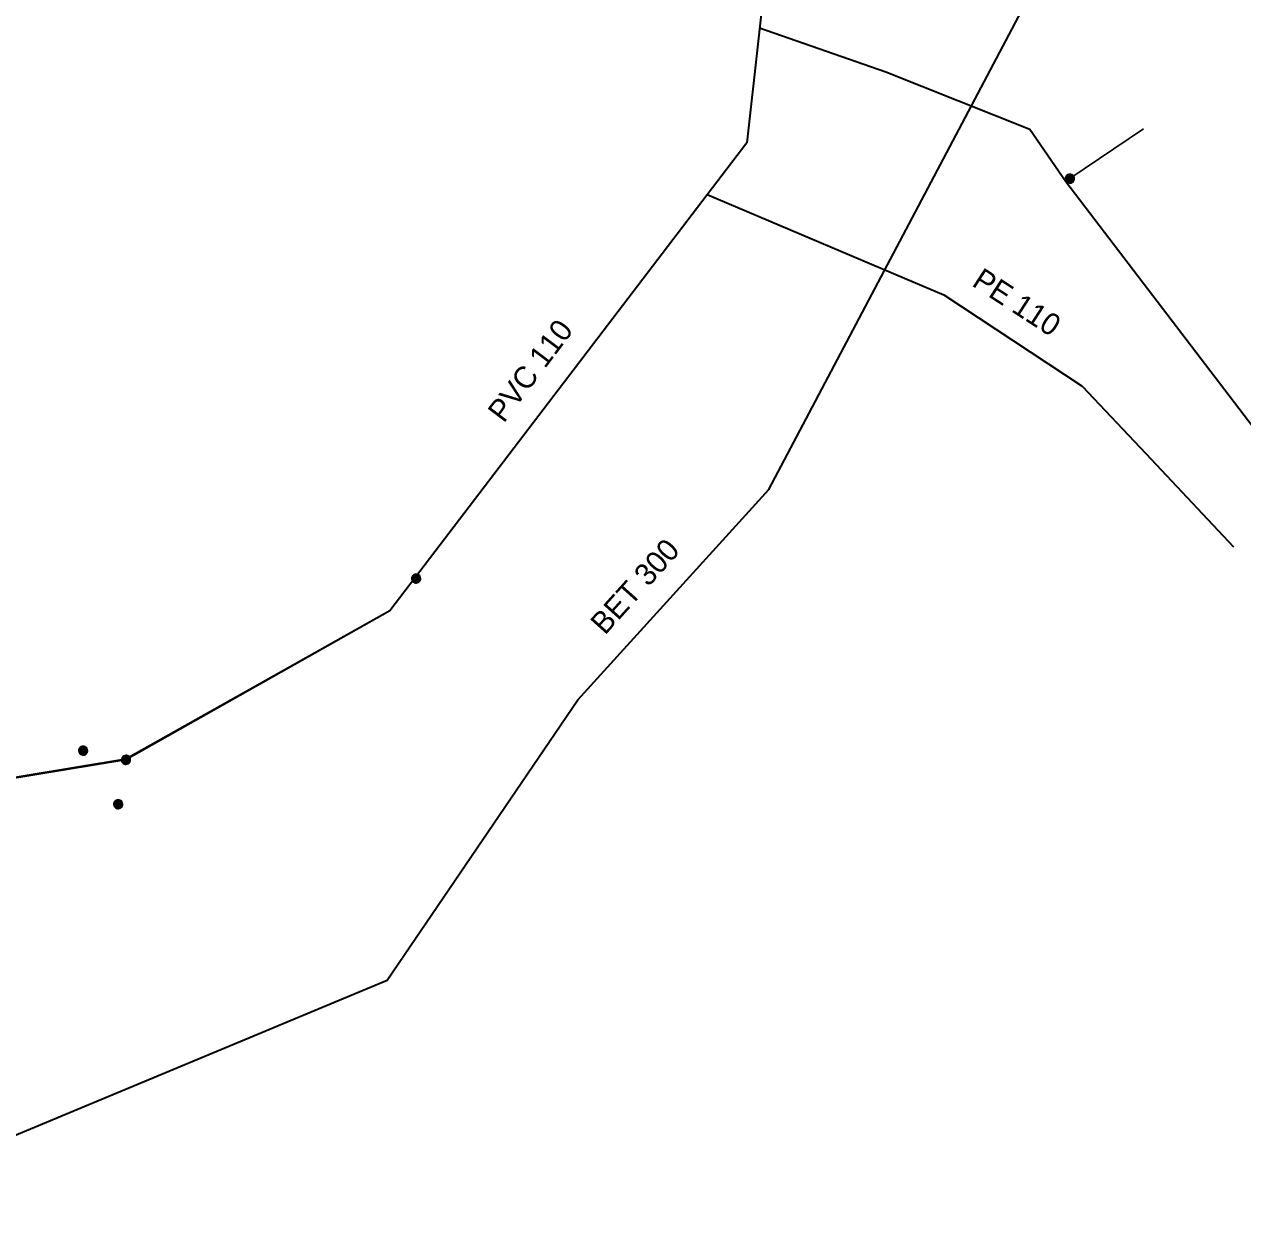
# Model space of a CAD drawing. Extents: x -873619 to -867639, y -1015082 to -1012326.
# Drawn here: x -868016.1 to -867954.9, y -1012860 to -1012799.5 of the extents above; entities that cross this region are included whole.
import ezdxf

# ---------------------------------------------------------------- set-up
doc = ezdxf.new("R2010")
doc.units = 0
doc.header["$LTSCALE"] = 0.44
for name, color, linetype, lineweight in [('1', 7, 'Continuous', 13), ('10', 7, 'Continuous', 13), ('12', 7, 'Continuous', 13), ('21', 7, 'Continuous', 35), ('25', 7, 'Continuous', 13), ('3', 7, 'Continuous', 25), ('32', 7, 'Continuous', 13)]:
    doc.layers.add(name, color=color, linetype=linetype, lineweight=lineweight)

msp = doc.modelspace()

# ---------------------------------------------------------------- linework, layer by layer
at = {"layer": '1', "lineweight": 35}
for points in [[(-867974.611, -1012725.697), (-867976.949, -1012730.385), (-867980.624, -1012763.205), (-867983.112, -1012775.195), (-867978.719, -1012795.525), (-867979.823, -1012805.464), (-867997.768, -1012829.005), (-868011.042, -1012836.499), (-868058.95, -1012844.4), (-868077.43, -1012833.46), (-868085.171, -1012827.86)], [(-867979.181, -1012799.683), (-867972.83, -1012801.89), (-867965.59, -1012804.78), (-867963.787, -1012807.409), (-867948.768, -1012827.087), (-867948.538, -1012827.407), (-867943.513, -1012834.828), (-867938.476, -1012842.701), (-867934.013, -1012848.778), (-867931.689, -1012852.506), (-867924.702, -1012862.569), (-867923.496, -1012864.901), (-867916.531, -1012874.592), (-867908.231, -1012887.091), (-867905.717, -1012890.99), (-867899.122, -1012900.29), (-867892.55, -1012910.082), (-867889.71, -1012914.412), (-867888.18, -1012916.7), (-867891.84, -1012919), (-867886.89, -1012927.31), (-867886.728, -1012931.158)], [(-867981.811, -1012808.072), (-867969.919, -1012813.11), (-867962.96, -1012817.7), (-867959.76, -1012821.1), (-867955.36, -1012825.78)], [(-867997.768, -1012829.005), (-868011.041, -1012836.459), (-868058.95, -1012844.4)]]:
    msp.add_lwpolyline(points, dxfattribs=at)
at = {"layer": '10'}
for points in [[(-867996.218, -1012827.381), (-867996.225, -1012827.329), (-867996.242, -1012827.279), (-867996.271, -1012827.235), (-867996.308, -1012827.198), (-867996.353, -1012827.171), (-867996.402, -1012827.154), (-867996.456, -1012827.15), (-867996.507, -1012827.157), (-867996.556, -1012827.176), (-867996.6, -1012827.205), (-867996.636, -1012827.244), (-867996.662, -1012827.289), (-867996.678, -1012827.34), (-867996.681, -1012827.392), (-867996.673, -1012827.444), (-867996.652, -1012827.493), (-867996.622, -1012827.536), (-867996.583, -1012827.57), (-867996.537, -1012827.596), (-867996.485, -1012827.61), (-867996.433, -1012827.612), (-867996.382, -1012827.602), (-867996.333, -1012827.581), (-867996.291, -1012827.55), (-867996.257, -1012827.509), (-867996.233, -1012827.463), (-867996.22, -1012827.412)], [(-867996.249, -1012827.381), (-867996.255, -1012827.332), (-867996.272, -1012827.286), (-867996.299, -1012827.246), (-867996.337, -1012827.214), (-867996.38, -1012827.192), (-867996.429, -1012827.181), (-867996.478, -1012827.181), (-867996.524, -1012827.194), (-867996.568, -1012827.218), (-867996.603, -1012827.251), (-867996.63, -1012827.292), (-867996.647, -1012827.339), (-867996.651, -1012827.388), (-867996.644, -1012827.436), (-867996.625, -1012827.481), (-867996.595, -1012827.521), (-867996.556, -1012827.552), (-867996.512, -1012827.572), (-867996.465, -1012827.582), (-867996.416, -1012827.58), (-867996.369, -1012827.565), (-867996.326, -1012827.54), (-867996.291, -1012827.506), (-867996.266, -1012827.464), (-867996.252, -1012827.417)], [(-867996.279, -1012827.381), (-867996.284, -1012827.336), (-867996.301, -1012827.294), (-867996.33, -1012827.259), (-867996.365, -1012827.232), (-867996.407, -1012827.215), (-867996.453, -1012827.21), (-867996.497, -1012827.216), (-867996.539, -1012827.235), (-867996.573, -1012827.263), (-867996.6, -1012827.3), (-867996.617, -1012827.342), (-867996.62, -1012827.387), (-867996.614, -1012827.432), (-867996.595, -1012827.473), (-867996.566, -1012827.507), (-867996.529, -1012827.533), (-867996.485, -1012827.549), (-867996.441, -1012827.552), (-867996.396, -1012827.544), (-867996.355, -1012827.524), (-867996.321, -1012827.495), (-867996.296, -1012827.457), (-867996.282, -1012827.414)], [(-867996.309, -1012827.381), (-867996.313, -1012827.34), (-867996.331, -1012827.303), (-867996.358, -1012827.272), (-867996.394, -1012827.251), (-867996.434, -1012827.24), (-867996.475, -1012827.242), (-867996.514, -1012827.255), (-867996.548, -1012827.279), (-867996.573, -1012827.311), (-867996.588, -1012827.349), (-867996.59, -1012827.39), (-867996.583, -1012827.43), (-867996.563, -1012827.466), (-867996.534, -1012827.495), (-867996.497, -1012827.514), (-867996.456, -1012827.522), (-867996.416, -1012827.518), (-867996.377, -1012827.503), (-867996.345, -1012827.477), (-867996.323, -1012827.443), (-867996.309, -1012827.404)], [(-867996.338, -1012827.381), (-867996.343, -1012827.345), (-867996.362, -1012827.313), (-867996.387, -1012827.288), (-867996.421, -1012827.273), (-867996.458, -1012827.27), (-867996.492, -1012827.278), (-867996.524, -1012827.298), (-867996.546, -1012827.326), (-867996.559, -1012827.36), (-867996.559, -1012827.397), (-867996.549, -1012827.432), (-867996.527, -1012827.461), (-867996.497, -1012827.482), (-867996.463, -1012827.492), (-867996.426, -1012827.49), (-867996.392, -1012827.476), (-867996.365, -1012827.453), (-867996.345, -1012827.421), (-867996.338, -1012827.386)], [(-867996.369, -1012827.381), (-867996.374, -1012827.35), (-867996.391, -1012827.324), (-867996.416, -1012827.307), (-867996.446, -1012827.3), (-867996.478, -1012827.304), (-867996.505, -1012827.321), (-867996.522, -1012827.345), (-867996.531, -1012827.376), (-867996.527, -1012827.406), (-867996.512, -1012827.434), (-867996.487, -1012827.453), (-867996.458, -1012827.462), (-867996.426, -1012827.459), (-867996.399, -1012827.445), (-867996.379, -1012827.421), (-867996.369, -1012827.392)], [(-867996.399, -1012827.381), (-867996.404, -1012827.357), (-867996.421, -1012827.339), (-867996.443, -1012827.33), (-867996.468, -1012827.333), (-867996.489, -1012827.347), (-867996.5, -1012827.369), (-867996.5, -1012827.394), (-867996.487, -1012827.415), (-867996.468, -1012827.429), (-867996.443, -1012827.432), (-867996.419, -1012827.423), (-867996.404, -1012827.405)], [(-867996.429, -1012827.381), (-867996.434, -1012827.366), (-867996.448, -1012827.36), (-867996.463, -1012827.364), (-867996.47, -1012827.378), (-867996.467, -1012827.393), (-867996.453, -1012827.402), (-867996.438, -1012827.399), (-867996.429, -1012827.387)], [(-868010.811, -1012836.499), (-868010.817, -1012836.447), (-868010.834, -1012836.397), (-868010.863, -1012836.353), (-868010.9, -1012836.316), (-868010.945, -1012836.289), (-868010.995, -1012836.272), (-868011.048, -1012836.268), (-868011.1, -1012836.275), (-868011.149, -1012836.294), (-868011.192, -1012836.323), (-868011.228, -1012836.362), (-868011.254, -1012836.407), (-868011.27, -1012836.458), (-868011.273, -1012836.51), (-868011.265, -1012836.562), (-868011.245, -1012836.611), (-868011.214, -1012836.654), (-868011.175, -1012836.688), (-868011.129, -1012836.714), (-868011.078, -1012836.728), (-868011.025, -1012836.73), (-868010.974, -1012836.72), (-868010.926, -1012836.699), (-868010.883, -1012836.668), (-868010.849, -1012836.627), (-868010.825, -1012836.581), (-868010.813, -1012836.53)], [(-868010.841, -1012836.499), (-868010.847, -1012836.45), (-868010.864, -1012836.404), (-868010.892, -1012836.364), (-868010.929, -1012836.332), (-868010.973, -1012836.31), (-868011.021, -1012836.299), (-868011.07, -1012836.299), (-868011.117, -1012836.312), (-868011.16, -1012836.336), (-868011.196, -1012836.369), (-868011.223, -1012836.41), (-868011.239, -1012836.457), (-868011.243, -1012836.506), (-868011.236, -1012836.554), (-868011.217, -1012836.599), (-868011.187, -1012836.639), (-868011.149, -1012836.67), (-868011.105, -1012836.69), (-868011.057, -1012836.7), (-868011.008, -1012836.698), (-868010.961, -1012836.683), (-868010.918, -1012836.658), (-868010.884, -1012836.624), (-868010.858, -1012836.582), (-868010.844, -1012836.535)], [(-868010.871, -1012836.499), (-868010.877, -1012836.454), (-868010.894, -1012836.412), (-868010.922, -1012836.377), (-868010.958, -1012836.35), (-868011, -1012836.333), (-868011.045, -1012836.328), (-868011.09, -1012836.334), (-868011.131, -1012836.353), (-868011.166, -1012836.381), (-868011.193, -1012836.418), (-868011.209, -1012836.46), (-868011.213, -1012836.505), (-868011.206, -1012836.55), (-868011.187, -1012836.591), (-868011.158, -1012836.625), (-868011.121, -1012836.651), (-868011.078, -1012836.667), (-868011.033, -1012836.67), (-868010.988, -1012836.662), (-868010.948, -1012836.642), (-868010.914, -1012836.613), (-868010.888, -1012836.575), (-868010.874, -1012836.532)], [(-868010.901, -1012836.499), (-868010.906, -1012836.458), (-868010.924, -1012836.421), (-868010.951, -1012836.39), (-868010.986, -1012836.369), (-868011.026, -1012836.358), (-868011.067, -1012836.36), (-868011.106, -1012836.373), (-868011.14, -1012836.397), (-868011.165, -1012836.429), (-868011.18, -1012836.467), (-868011.183, -1012836.508), (-868011.175, -1012836.548), (-868011.155, -1012836.584), (-868011.126, -1012836.613), (-868011.089, -1012836.632), (-868011.049, -1012836.64), (-868011.008, -1012836.636), (-868010.97, -1012836.621), (-868010.938, -1012836.595), (-868010.915, -1012836.561), (-868010.902, -1012836.522)], [(-868010.931, -1012836.499), (-868010.936, -1012836.463), (-868010.954, -1012836.431), (-868010.98, -1012836.406), (-868011.014, -1012836.391), (-868011.05, -1012836.388), (-868011.085, -1012836.396), (-868011.116, -1012836.416), (-868011.139, -1012836.444), (-868011.152, -1012836.478), (-868011.152, -1012836.515), (-868011.141, -1012836.55), (-868011.12, -1012836.579), (-868011.09, -1012836.6), (-868011.055, -1012836.61), (-868011.018, -1012836.608), (-868010.984, -1012836.594), (-868010.957, -1012836.571), (-868010.938, -1012836.539), (-868010.931, -1012836.504)], [(-868010.961, -1012836.499), (-868010.966, -1012836.468), (-868010.983, -1012836.442), (-868011.009, -1012836.425), (-868011.039, -1012836.418), (-868011.07, -1012836.422), (-868011.097, -1012836.439), (-868011.115, -1012836.463), (-868011.123, -1012836.494), (-868011.119, -1012836.524), (-868011.104, -1012836.552), (-868011.08, -1012836.571), (-868011.05, -1012836.58), (-868011.019, -1012836.577), (-868010.991, -1012836.563), (-868010.971, -1012836.539), (-868010.961, -1012836.51)], [(-868010.991, -1012836.499), (-868010.996, -1012836.475), (-868011.013, -1012836.457), (-868011.036, -1012836.448), (-868011.06, -1012836.451), (-868011.081, -1012836.465), (-868011.092, -1012836.487), (-868011.092, -1012836.512), (-868011.08, -1012836.533), (-868011.06, -1012836.547), (-868011.035, -1012836.55), (-868011.012, -1012836.541), (-868010.996, -1012836.523)], [(-868011.021, -1012836.499), (-868011.026, -1012836.484), (-868011.041, -1012836.478), (-868011.056, -1012836.482), (-868011.063, -1012836.496), (-868011.059, -1012836.511), (-868011.046, -1012836.52), (-868011.031, -1012836.517), (-868011.021, -1012836.505)]]:
    msp.add_lwpolyline(points, close=True, dxfattribs=at)
at = {"layer": '12'}
for points in [[(-867963.348, -1012807.27), (-867963.355, -1012807.218), (-867963.372, -1012807.168), (-867963.401, -1012807.124), (-867963.438, -1012807.087), (-867963.483, -1012807.06), (-867963.532, -1012807.043), (-867963.586, -1012807.039), (-867963.637, -1012807.046), (-867963.686, -1012807.065), (-867963.73, -1012807.094), (-867963.766, -1012807.133), (-867963.792, -1012807.178), (-867963.808, -1012807.229), (-867963.811, -1012807.281), (-867963.803, -1012807.333), (-867963.782, -1012807.382), (-867963.752, -1012807.425), (-867963.713, -1012807.459), (-867963.667, -1012807.485), (-867963.615, -1012807.499), (-867963.563, -1012807.501), (-867963.512, -1012807.491), (-867963.463, -1012807.47), (-867963.421, -1012807.439), (-867963.387, -1012807.398), (-867963.363, -1012807.352), (-867963.35, -1012807.301)], [(-867963.379, -1012807.27), (-867963.385, -1012807.221), (-867963.402, -1012807.175), (-867963.429, -1012807.135), (-867963.467, -1012807.103), (-867963.511, -1012807.081), (-867963.559, -1012807.07), (-867963.608, -1012807.07), (-867963.654, -1012807.083), (-867963.698, -1012807.107), (-867963.733, -1012807.14), (-867963.761, -1012807.181), (-867963.777, -1012807.228), (-867963.781, -1012807.277), (-867963.774, -1012807.325), (-867963.755, -1012807.37), (-867963.725, -1012807.41), (-867963.686, -1012807.441), (-867963.642, -1012807.461), (-867963.595, -1012807.471), (-867963.546, -1012807.469), (-867963.499, -1012807.454), (-867963.456, -1012807.429), (-867963.421, -1012807.395), (-867963.396, -1012807.353), (-867963.382, -1012807.306)], [(-867963.409, -1012807.27), (-867963.414, -1012807.225), (-867963.431, -1012807.183), (-867963.46, -1012807.148), (-867963.495, -1012807.121), (-867963.538, -1012807.104), (-867963.583, -1012807.099), (-867963.627, -1012807.105), (-867963.669, -1012807.124), (-867963.703, -1012807.152), (-867963.73, -1012807.189), (-867963.747, -1012807.231), (-867963.75, -1012807.276), (-867963.744, -1012807.321), (-867963.725, -1012807.362), (-867963.696, -1012807.396), (-867963.659, -1012807.422), (-867963.615, -1012807.438), (-867963.571, -1012807.441), (-867963.526, -1012807.433), (-867963.485, -1012807.413), (-867963.451, -1012807.384), (-867963.426, -1012807.346), (-867963.412, -1012807.303)], [(-867963.439, -1012807.27), (-867963.443, -1012807.229), (-867963.462, -1012807.192), (-867963.489, -1012807.161), (-867963.524, -1012807.14), (-867963.564, -1012807.129), (-867963.605, -1012807.131), (-867963.644, -1012807.144), (-867963.678, -1012807.168), (-867963.703, -1012807.2), (-867963.718, -1012807.238), (-867963.72, -1012807.279), (-867963.713, -1012807.319), (-867963.693, -1012807.355), (-867963.664, -1012807.384), (-867963.627, -1012807.403), (-867963.587, -1012807.411), (-867963.546, -1012807.407), (-867963.507, -1012807.392), (-867963.475, -1012807.366), (-867963.453, -1012807.332), (-867963.44, -1012807.293)], [(-867963.468, -1012807.27), (-867963.473, -1012807.234), (-867963.492, -1012807.202), (-867963.517, -1012807.177), (-867963.551, -1012807.162), (-867963.588, -1012807.159), (-867963.622, -1012807.167), (-867963.654, -1012807.187), (-867963.676, -1012807.215), (-867963.69, -1012807.249), (-867963.69, -1012807.286), (-867963.679, -1012807.321), (-867963.657, -1012807.35), (-867963.627, -1012807.371), (-867963.593, -1012807.381), (-867963.556, -1012807.379), (-867963.522, -1012807.365), (-867963.495, -1012807.342), (-867963.475, -1012807.31), (-867963.468, -1012807.275)], [(-867963.499, -1012807.27), (-867963.504, -1012807.239), (-867963.521, -1012807.213), (-867963.546, -1012807.196), (-867963.576, -1012807.189), (-867963.608, -1012807.193), (-867963.635, -1012807.21), (-867963.652, -1012807.234), (-867963.661, -1012807.265), (-867963.657, -1012807.295), (-867963.642, -1012807.323), (-867963.617, -1012807.342), (-867963.588, -1012807.351), (-867963.556, -1012807.348), (-867963.529, -1012807.334), (-867963.509, -1012807.31), (-867963.499, -1012807.281)], [(-867963.529, -1012807.27), (-867963.534, -1012807.246), (-867963.551, -1012807.228), (-867963.573, -1012807.219), (-867963.598, -1012807.222), (-867963.619, -1012807.236), (-867963.63, -1012807.258), (-867963.63, -1012807.283), (-867963.617, -1012807.304), (-867963.598, -1012807.318), (-867963.573, -1012807.321), (-867963.549, -1012807.312), (-867963.534, -1012807.294)], [(-867963.559, -1012807.27), (-867963.564, -1012807.255), (-867963.578, -1012807.249), (-867963.593, -1012807.253), (-867963.6, -1012807.267), (-867963.597, -1012807.282), (-867963.583, -1012807.291), (-867963.568, -1012807.288), (-867963.559, -1012807.276)]]:
    msp.add_lwpolyline(points, close=True, dxfattribs=at)
at = {"layer": '21'}
msp.add_lwpolyline([(-868020.287, -1012856.898), (-867997.903, -1012847.584), (-867988.318, -1012833.474), (-867978.718, -1012822.899), (-867965.69, -1012798.22), (-867965.665, -1012798.299)], dxfattribs=at)
at = {"layer": '25'}
for points in [[(-868011.199, -1012838.73), (-868011.205, -1012838.678), (-868011.222, -1012838.628), (-868011.251, -1012838.584), (-868011.288, -1012838.547), (-868011.333, -1012838.52), (-868011.383, -1012838.503), (-868011.436, -1012838.499), (-868011.488, -1012838.506), (-868011.537, -1012838.525), (-868011.58, -1012838.554), (-868011.616, -1012838.593), (-868011.642, -1012838.638), (-868011.658, -1012838.689), (-868011.661, -1012838.741), (-868011.653, -1012838.793), (-868011.633, -1012838.842), (-868011.602, -1012838.885), (-868011.563, -1012838.919), (-868011.517, -1012838.945), (-868011.466, -1012838.959), (-868011.413, -1012838.961), (-868011.362, -1012838.951), (-868011.314, -1012838.93), (-868011.271, -1012838.899), (-868011.237, -1012838.858), (-868011.213, -1012838.812), (-868011.201, -1012838.761)], [(-868011.229, -1012838.73), (-868011.235, -1012838.681), (-868011.252, -1012838.635), (-868011.28, -1012838.595), (-868011.317, -1012838.563), (-868011.361, -1012838.541), (-868011.409, -1012838.53), (-868011.458, -1012838.53), (-868011.505, -1012838.543), (-868011.548, -1012838.567), (-868011.584, -1012838.6), (-868011.611, -1012838.641), (-868011.627, -1012838.688), (-868011.631, -1012838.737), (-868011.624, -1012838.785), (-868011.605, -1012838.83), (-868011.575, -1012838.87), (-868011.537, -1012838.901), (-868011.493, -1012838.921), (-868011.445, -1012838.931), (-868011.396, -1012838.929), (-868011.349, -1012838.914), (-868011.306, -1012838.889), (-868011.272, -1012838.855), (-868011.246, -1012838.813), (-868011.232, -1012838.766)], [(-868011.259, -1012838.73), (-868011.265, -1012838.685), (-868011.282, -1012838.643), (-868011.31, -1012838.608), (-868011.346, -1012838.581), (-868011.388, -1012838.564), (-868011.433, -1012838.559), (-868011.478, -1012838.565), (-868011.519, -1012838.584), (-868011.554, -1012838.612), (-868011.581, -1012838.649), (-868011.597, -1012838.691), (-868011.601, -1012838.736), (-868011.594, -1012838.781), (-868011.575, -1012838.822), (-868011.546, -1012838.856), (-868011.509, -1012838.882), (-868011.466, -1012838.898), (-868011.421, -1012838.901), (-868011.376, -1012838.893), (-868011.336, -1012838.873), (-868011.302, -1012838.844), (-868011.276, -1012838.806), (-868011.262, -1012838.763)], [(-868011.289, -1012838.73), (-868011.294, -1012838.689), (-868011.312, -1012838.652), (-868011.339, -1012838.621), (-868011.374, -1012838.6), (-868011.414, -1012838.589), (-868011.455, -1012838.591), (-868011.494, -1012838.604), (-868011.528, -1012838.628), (-868011.553, -1012838.66), (-868011.568, -1012838.698), (-868011.571, -1012838.739), (-868011.563, -1012838.779), (-868011.543, -1012838.815), (-868011.514, -1012838.844), (-868011.477, -1012838.863), (-868011.437, -1012838.871), (-868011.396, -1012838.867), (-868011.358, -1012838.852), (-868011.326, -1012838.826), (-868011.303, -1012838.792), (-868011.29, -1012838.753)], [(-868011.319, -1012838.73), (-868011.324, -1012838.694), (-868011.342, -1012838.662), (-868011.368, -1012838.637), (-868011.402, -1012838.622), (-868011.438, -1012838.619), (-868011.473, -1012838.627), (-868011.504, -1012838.647), (-868011.527, -1012838.675), (-868011.54, -1012838.709), (-868011.54, -1012838.746), (-868011.529, -1012838.781), (-868011.508, -1012838.81), (-868011.478, -1012838.831), (-868011.443, -1012838.841), (-868011.406, -1012838.839), (-868011.372, -1012838.825), (-868011.345, -1012838.802), (-868011.326, -1012838.77), (-868011.319, -1012838.735)], [(-868011.349, -1012838.73), (-868011.354, -1012838.699), (-868011.371, -1012838.673), (-868011.397, -1012838.656), (-868011.427, -1012838.649), (-868011.458, -1012838.653), (-868011.485, -1012838.67), (-868011.503, -1012838.694), (-868011.511, -1012838.725), (-868011.507, -1012838.755), (-868011.492, -1012838.783), (-868011.468, -1012838.802), (-868011.438, -1012838.811), (-868011.407, -1012838.808), (-868011.379, -1012838.794), (-868011.359, -1012838.77), (-868011.349, -1012838.741)], [(-868011.379, -1012838.73), (-868011.384, -1012838.706), (-868011.401, -1012838.688), (-868011.424, -1012838.679), (-868011.448, -1012838.682), (-868011.469, -1012838.696), (-868011.48, -1012838.718), (-868011.48, -1012838.743), (-868011.468, -1012838.764), (-868011.448, -1012838.778), (-868011.423, -1012838.781), (-868011.4, -1012838.772), (-868011.384, -1012838.754)], [(-868011.409, -1012838.73), (-868011.414, -1012838.715), (-868011.429, -1012838.709), (-868011.444, -1012838.713), (-868011.451, -1012838.727), (-868011.447, -1012838.742), (-868011.434, -1012838.751), (-868011.419, -1012838.748), (-868011.409, -1012838.736)]]:
    msp.add_lwpolyline(points, close=True, dxfattribs=at)
at = {"layer": '3'}
msp.add_lwpolyline([(-867963.787, -1012807.409), (-867963.58, -1012807.27), (-867959.873, -1012804.772)], dxfattribs=at)
at = {"layer": '32'}
for points in [[(-868012.958, -1012836.04), (-868012.965, -1012835.988), (-868012.982, -1012835.938), (-868013.011, -1012835.894), (-868013.048, -1012835.857), (-868013.093, -1012835.83), (-868013.142, -1012835.813), (-868013.196, -1012835.809), (-868013.247, -1012835.816), (-868013.296, -1012835.835), (-868013.34, -1012835.864), (-868013.375, -1012835.903), (-868013.402, -1012835.948), (-868013.418, -1012835.999), (-868013.421, -1012836.051), (-868013.413, -1012836.103), (-868013.392, -1012836.152), (-868013.362, -1012836.195), (-868013.323, -1012836.229), (-868013.277, -1012836.255), (-868013.225, -1012836.269), (-868013.173, -1012836.271), (-868013.122, -1012836.261), (-868013.073, -1012836.24), (-868013.031, -1012836.209), (-868012.997, -1012836.168), (-868012.973, -1012836.122), (-868012.96, -1012836.071)], [(-868012.989, -1012836.04), (-868012.995, -1012835.991), (-868013.012, -1012835.945), (-868013.039, -1012835.905), (-868013.076, -1012835.873), (-868013.12, -1012835.851), (-868013.169, -1012835.84), (-868013.218, -1012835.84), (-868013.264, -1012835.853), (-868013.308, -1012835.877), (-868013.343, -1012835.91), (-868013.37, -1012835.951), (-868013.387, -1012835.998), (-868013.391, -1012836.047), (-868013.384, -1012836.095), (-868013.365, -1012836.14), (-868013.335, -1012836.18), (-868013.296, -1012836.211), (-868013.252, -1012836.231), (-868013.205, -1012836.241), (-868013.156, -1012836.239), (-868013.108, -1012836.224), (-868013.066, -1012836.199), (-868013.031, -1012836.165), (-868013.005, -1012836.123), (-868012.992, -1012836.076)], [(-868013.019, -1012836.04), (-868013.024, -1012835.995), (-868013.041, -1012835.953), (-868013.07, -1012835.918), (-868013.105, -1012835.891), (-868013.147, -1012835.874), (-868013.193, -1012835.869), (-868013.237, -1012835.875), (-868013.279, -1012835.894), (-868013.313, -1012835.922), (-868013.34, -1012835.959), (-868013.357, -1012836.001), (-868013.36, -1012836.046), (-868013.353, -1012836.091), (-868013.335, -1012836.132), (-868013.306, -1012836.166), (-868013.269, -1012836.192), (-868013.225, -1012836.208), (-868013.181, -1012836.211), (-868013.136, -1012836.203), (-868013.095, -1012836.183), (-868013.061, -1012836.154), (-868013.036, -1012836.116), (-868013.022, -1012836.073)], [(-868013.049, -1012836.04), (-868013.053, -1012835.999), (-868013.071, -1012835.962), (-868013.098, -1012835.931), (-868013.134, -1012835.91), (-868013.174, -1012835.899), (-868013.215, -1012835.901), (-868013.254, -1012835.914), (-868013.288, -1012835.938), (-868013.313, -1012835.97), (-868013.328, -1012836.008), (-868013.33, -1012836.049), (-868013.323, -1012836.089), (-868013.303, -1012836.125), (-868013.274, -1012836.154), (-868013.237, -1012836.173), (-868013.196, -1012836.181), (-868013.156, -1012836.177), (-868013.117, -1012836.162), (-868013.085, -1012836.136), (-868013.063, -1012836.102), (-868013.049, -1012836.063)], [(-868013.078, -1012836.04), (-868013.083, -1012836.004), (-868013.102, -1012835.972), (-868013.127, -1012835.947), (-868013.161, -1012835.932), (-868013.198, -1012835.929), (-868013.232, -1012835.937), (-868013.264, -1012835.957), (-868013.286, -1012835.985), (-868013.299, -1012836.019), (-868013.299, -1012836.056), (-868013.289, -1012836.091), (-868013.267, -1012836.12), (-868013.237, -1012836.141), (-868013.203, -1012836.151), (-868013.166, -1012836.149), (-868013.132, -1012836.135), (-868013.105, -1012836.112), (-868013.085, -1012836.08), (-868013.078, -1012836.045)], [(-868013.108, -1012836.04), (-868013.114, -1012836.009), (-868013.13, -1012835.983), (-868013.156, -1012835.966), (-868013.186, -1012835.959), (-868013.218, -1012835.963), (-868013.245, -1012835.98), (-868013.262, -1012836.004), (-868013.271, -1012836.035), (-868013.267, -1012836.065), (-868013.252, -1012836.093), (-868013.227, -1012836.112), (-868013.198, -1012836.121), (-868013.166, -1012836.118), (-868013.139, -1012836.104), (-868013.119, -1012836.08), (-868013.108, -1012836.051)], [(-868013.139, -1012836.04), (-868013.144, -1012836.016), (-868013.161, -1012835.998), (-868013.183, -1012835.989), (-868013.208, -1012835.992), (-868013.228, -1012836.006), (-868013.24, -1012836.028), (-868013.24, -1012836.053), (-868013.227, -1012836.074), (-868013.208, -1012836.088), (-868013.183, -1012836.091), (-868013.159, -1012836.082), (-868013.144, -1012836.064)], [(-868013.169, -1012836.04), (-868013.174, -1012836.025), (-868013.188, -1012836.019), (-868013.203, -1012836.023), (-868013.21, -1012836.037), (-868013.206, -1012836.052), (-868013.193, -1012836.061), (-868013.178, -1012836.058), (-868013.169, -1012836.046)]]:
    msp.add_lwpolyline(points, close=True, dxfattribs=at)

# ---------------------------------------------------------------- texts
at = {"layer": '1'}
for s, rotation, p in [('PE 110', 327, (-867968.561, -1012812.627)), ('PVC 110 ', 53, (-867992.043, -1012819.599)), ('BET 300 ', 48, (-867986.957, -1012830.264))]:
    msp.add_text(s, height=1.1, rotation=rotation, dxfattribs=at).set_placement(p)

doc.saveas('drawing.dxf')
